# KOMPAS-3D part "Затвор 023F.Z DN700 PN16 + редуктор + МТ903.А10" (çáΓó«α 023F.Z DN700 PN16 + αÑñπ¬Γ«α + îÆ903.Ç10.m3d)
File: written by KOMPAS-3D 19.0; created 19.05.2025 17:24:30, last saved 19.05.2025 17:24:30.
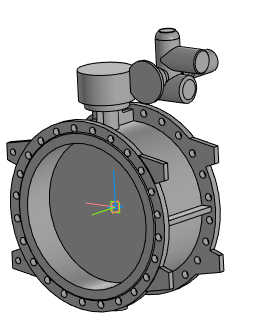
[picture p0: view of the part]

Document properties: Полное имя файла: Затвор 023F.Z DN700 PN16 + редуктор + МТ903.А10.a3d

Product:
- Part/product: Затвор 023F.Z DN700 PN16 + редуктор + МТ903.А10
    Масса: 671.028

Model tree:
1. Операция без истории:1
